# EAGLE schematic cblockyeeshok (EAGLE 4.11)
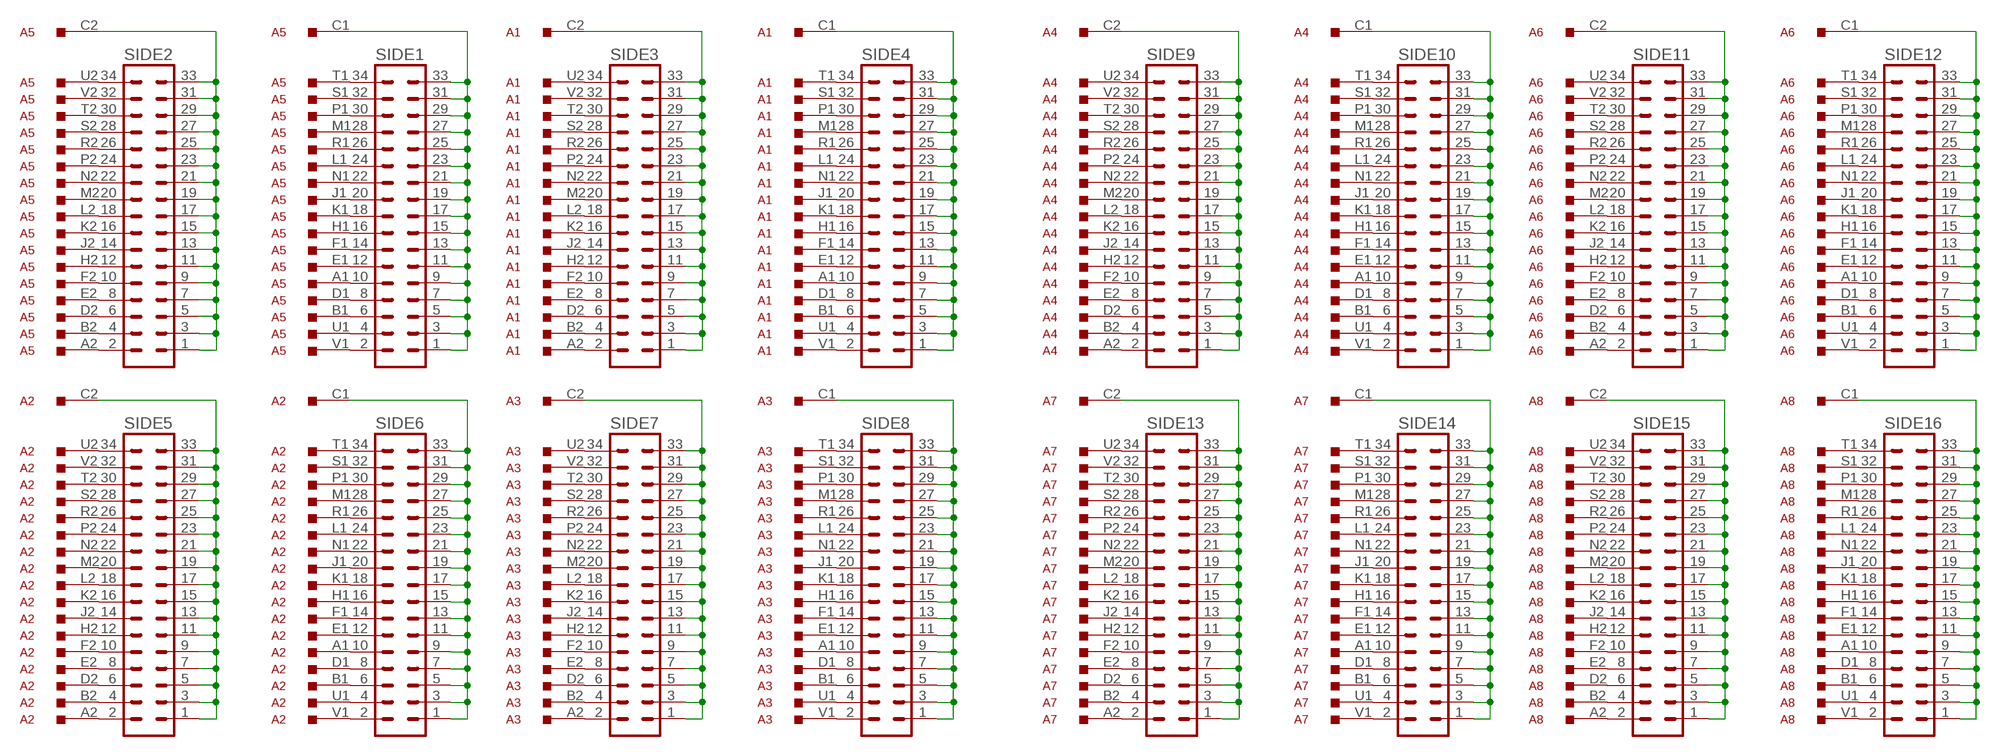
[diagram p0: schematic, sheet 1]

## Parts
A1  M916  [H807]
A2  M916  [H807]
A3  M916  [H807]
A4  M916  [H807]
A5  M916  [H807]
A6  M916  [H807]
A7  M916  [H807]
A8  M916  [H807]
SIDE1  MA17-2  [MA17-2]
SIDE2  MA17-2  [MA17-2]
SIDE3  MA17-2  [MA17-2]
SIDE4  MA17-2  [MA17-2]
SIDE5  MA17-2  [MA17-2]
SIDE6  MA17-2  [MA17-2]
SIDE7  MA17-2  [MA17-2]
SIDE8  MA17-2  [MA17-2]
SIDE9  MA17-2  [MA17-2]
SIDE10  MA17-2  [MA17-2]
SIDE11  MA17-2  [MA17-2]
SIDE12  MA17-2  [MA17-2]
SIDE13  MA17-2  [MA17-2]
SIDE14  MA17-2  [MA17-2]
SIDE15  MA17-2  [MA17-2]
SIDE16  MA17-2  [MA17-2]

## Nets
N$1: A5.C2 SIDE2.1 SIDE2.3 SIDE2.5 SIDE2.7 SIDE2.9 SIDE2.11 SIDE2.13 SIDE2.15 SIDE2.17 SIDE2.19 SIDE2.21 SIDE2.23 SIDE2.25 SIDE2.27 SIDE2.29 SIDE2.31 SIDE2.33
N$2: A5.A2 SIDE2.2
N$3: A5.B2 SIDE2.4
N$4: A5.D2 SIDE2.6
N$5: A5.E2 SIDE2.8
N$6: A5.F2 SIDE2.10
N$7: A5.H2 SIDE2.12
N$8: A5.J2 SIDE2.14
N$9: A5.K2 SIDE2.16
N$10: A5.L2 SIDE2.18
N$11: A5.M2 SIDE2.20
N$12: A5.N2 SIDE2.22
N$13: A5.P2 SIDE2.24
N$14: A5.R2 SIDE2.26
N$15: A5.S2 SIDE2.28
N$16: A5.T2 SIDE2.30
N$17: A5.U2 SIDE2.34
N$18: A5.V2 SIDE2.32
N$19: A5.A1 SIDE1.10
N$20: A5.B1 SIDE1.6
N$21: A5.D1 SIDE1.8
N$22: A5.E1 SIDE1.12
N$23: A5.F1 SIDE1.14
N$24: A5.H1 SIDE1.16
N$25: A5.J1 SIDE1.20
N$26: A5.K1 SIDE1.18
N$27: A5.L1 SIDE1.24
N$28: A5.M1 SIDE1.28
N$29: A5.N1 SIDE1.22
N$30: A5.P1 SIDE1.30
N$31: A5.R1 SIDE1.26
N$32: A5.S1 SIDE1.32
N$33: A5.T1 SIDE1.34
N$34: A5.U1 SIDE1.4
N$35: A5.V1 SIDE1.2
N$36: A5.C1 SIDE1.1 SIDE1.3 SIDE1.5 SIDE1.7 SIDE1.9 SIDE1.11 SIDE1.13 SIDE1.15 SIDE1.17 SIDE1.19 SIDE1.21 SIDE1.23 SIDE1.25 SIDE1.27 SIDE1.29 SIDE1.31 SIDE1.33
N$37: A1.C2 SIDE3.1 SIDE3.3 SIDE3.5 SIDE3.7 SIDE3.9 SIDE3.11 SIDE3.13 SIDE3.15 SIDE3.17 SIDE3.19 SIDE3.21 SIDE3.23 SIDE3.25 SIDE3.27 SIDE3.29 SIDE3.31 SIDE3.33
N$38: A1.A2 SIDE3.2
N$39: A1.B2 SIDE3.4
N$40: A1.D2 SIDE3.6
N$41: A1.E2 SIDE3.8
N$42: A1.F2 SIDE3.10
N$43: A1.H2 SIDE3.12
N$44: A1.J2 SIDE3.14
N$45: A1.K2 SIDE3.16
N$46: A1.L2 SIDE3.18
N$47: A1.M2 SIDE3.20
N$48: A1.N2 SIDE3.22
N$49: A1.P2 SIDE3.24
N$50: A1.R2 SIDE3.26
N$51: A1.S2 SIDE3.28
N$52: A1.T2 SIDE3.30
N$53: A1.U2 SIDE3.34
N$54: A1.V2 SIDE3.32
N$55: A1.A1 SIDE4.10
N$56: A1.B1 SIDE4.6
N$57: A1.D1 SIDE4.8
N$58: A1.E1 SIDE4.12
N$59: A1.F1 SIDE4.14
N$60: A1.H1 SIDE4.16
N$61: A1.J1 SIDE4.20
N$62: A1.K1 SIDE4.18
N$63: A1.L1 SIDE4.24
N$64: A1.M1 SIDE4.28
N$65: A1.N1 SIDE4.22
N$66: A1.P1 SIDE4.30
N$67: A1.R1 SIDE4.26
N$68: A1.S1 SIDE4.32
N$69: A1.T1 SIDE4.34
N$70: A1.U1 SIDE4.4
N$71: A1.V1 SIDE4.2
N$72: A1.C1 SIDE4.1 SIDE4.3 SIDE4.5 SIDE4.7 SIDE4.9 SIDE4.11 SIDE4.13 SIDE4.15 SIDE4.17 SIDE4.19 SIDE4.21 SIDE4.23 SIDE4.25 SIDE4.27 SIDE4.29 SIDE4.31 SIDE4.33
N$73: A2.C2 SIDE5.1 SIDE5.3 SIDE5.5 SIDE5.7 SIDE5.9 SIDE5.11 SIDE5.13 SIDE5.15 SIDE5.17 SIDE5.19 SIDE5.21 SIDE5.23 SIDE5.25 SIDE5.27 SIDE5.29 SIDE5.31 SIDE5.33
N$74: A2.A2 SIDE5.2
N$75: A2.B2 SIDE5.4
N$76: A2.D2 SIDE5.6
N$77: A2.E2 SIDE5.8
N$78: A2.F2 SIDE5.10
N$79: A2.H2 SIDE5.12
N$80: A2.J2 SIDE5.14
N$81: A2.K2 SIDE5.16
N$82: A2.L2 SIDE5.18
N$83: A2.M2 SIDE5.20
N$84: A2.N2 SIDE5.22
N$85: A2.P2 SIDE5.24
N$86: A2.R2 SIDE5.26
N$87: A2.S2 SIDE5.28
N$88: A2.T2 SIDE5.30
N$89: A2.U2 SIDE5.34
N$90: A2.V2 SIDE5.32
N$91: A2.A1 SIDE6.10
N$92: A2.B1 SIDE6.6
N$93: A2.D1 SIDE6.8
N$94: A2.E1 SIDE6.12
N$95: A2.F1 SIDE6.14
N$96: A2.H1 SIDE6.16
N$97: A2.J1 SIDE6.20
N$98: A2.K1 SIDE6.18
N$99: A2.L1 SIDE6.24
N$100: A2.M1 SIDE6.28
N$101: A2.N1 SIDE6.22
N$102: A2.P1 SIDE6.30
N$103: A2.R1 SIDE6.26
N$104: A2.S1 SIDE6.32
N$105: A2.T1 SIDE6.34
N$106: A2.U1 SIDE6.4
N$107: A2.V1 SIDE6.2
N$108: A2.C1 SIDE6.1 SIDE6.3 SIDE6.5 SIDE6.7 SIDE6.9 SIDE6.11 SIDE6.13 SIDE6.15 SIDE6.17 SIDE6.19 SIDE6.21 SIDE6.23 SIDE6.25 SIDE6.27 SIDE6.29 SIDE6.31 SIDE6.33
N$109: A3.C2 SIDE7.1 SIDE7.3 SIDE7.5 SIDE7.7 SIDE7.9 SIDE7.11 SIDE7.13 SIDE7.15 SIDE7.17 SIDE7.19 SIDE7.21 SIDE7.23 SIDE7.25 SIDE7.27 SIDE7.29 SIDE7.31 SIDE7.33
N$110: A3.A2 SIDE7.2
N$111: A3.B2 SIDE7.4
N$112: A3.D2 SIDE7.6
N$113: A3.E2 SIDE7.8
N$114: A3.F2 SIDE7.10
N$115: A3.H2 SIDE7.12
N$116: A3.J2 SIDE7.14
N$117: A3.K2 SIDE7.16
N$118: A3.L2 SIDE7.18
N$119: A3.M2 SIDE7.20
N$120: A3.N2 SIDE7.22
N$121: A3.P2 SIDE7.24
N$122: A3.R2 SIDE7.26
N$123: A3.S2 SIDE7.28
N$124: A3.T2 SIDE7.30
N$125: A3.U2 SIDE7.34
N$126: A3.V2 SIDE7.32
N$127: A3.A1 SIDE8.10
N$128: A3.B1 SIDE8.6
N$129: A3.D1 SIDE8.8
N$130: A3.E1 SIDE8.12
N$131: A3.F1 SIDE8.14
N$132: A3.H1 SIDE8.16
N$133: A3.J1 SIDE8.20
N$134: A3.K1 SIDE8.18
N$135: A3.L1 SIDE8.24
N$136: A3.M1 SIDE8.28
N$137: A3.N1 SIDE8.22
N$138: A3.P1 SIDE8.30
N$139: A3.R1 SIDE8.26
N$140: A3.S1 SIDE8.32
N$141: A3.T1 SIDE8.34
N$142: A3.U1 SIDE8.4
N$143: A3.V1 SIDE8.2
N$144: A3.C1 SIDE8.1 SIDE8.3 SIDE8.5 SIDE8.7 SIDE8.9 SIDE8.11 SIDE8.13 SIDE8.15 SIDE8.17 SIDE8.19 SIDE8.21 SIDE8.23 SIDE8.25 SIDE8.27 SIDE8.29 SIDE8.31 SIDE8.33
N$145: A4.C2 SIDE9.1 SIDE9.3 SIDE9.5 SIDE9.7 SIDE9.9 SIDE9.11 SIDE9.13 SIDE9.15 SIDE9.17 SIDE9.19 SIDE9.21 SIDE9.23 SIDE9.25 SIDE9.27 SIDE9.29 SIDE9.31 SIDE9.33
N$146: A4.A2 SIDE9.2
N$147: A4.B2 SIDE9.4
N$148: A4.D2 SIDE9.6
N$149: A4.E2 SIDE9.8
N$150: A4.F2 SIDE9.10
N$151: A4.H2 SIDE9.12
N$152: A4.J2 SIDE9.14
N$153: A4.K2 SIDE9.16
N$154: A4.L2 SIDE9.18
N$155: A4.M2 SIDE9.20
N$156: A4.N2 SIDE9.22
N$157: A4.P2 SIDE9.24
N$158: A4.R2 SIDE9.26
N$159: A4.S2 SIDE9.28
N$160: A4.T2 SIDE9.30
N$161: A4.U2 SIDE9.34
N$162: A4.V2 SIDE9.32
N$163: A4.A1 SIDE10.10
N$164: A4.B1 SIDE10.6
N$165: A4.D1 SIDE10.8
N$166: A4.E1 SIDE10.12
N$167: A4.F1 SIDE10.14
N$168: A4.H1 SIDE10.16
N$169: A4.J1 SIDE10.20
N$170: A4.K1 SIDE10.18
N$171: A4.L1 SIDE10.24
N$172: A4.M1 SIDE10.28
N$173: A4.N1 SIDE10.22
N$174: A4.P1 SIDE10.30
N$175: A4.R1 SIDE10.26
N$176: A4.S1 SIDE10.32
N$177: A4.T1 SIDE10.34
N$178: A4.U1 SIDE10.4
N$179: A4.V1 SIDE10.2
N$180: A4.C1 SIDE10.1 SIDE10.3 SIDE10.5 SIDE10.7 SIDE10.9 SIDE10.11 SIDE10.13 SIDE10.15 SIDE10.17 SIDE10.19 SIDE10.21 SIDE10.23 SIDE10.25 SIDE10.27 SIDE10.29 SIDE10.31 SIDE10.33
N$181: A6.C2 SIDE11.1 SIDE11.3 SIDE11.5 SIDE11.7 SIDE11.9 SIDE11.11 SIDE11.13 SIDE11.15 SIDE11.17 SIDE11.19 SIDE11.21 SIDE11.23 SIDE11.25 SIDE11.27 SIDE11.29 SIDE11.31 SIDE11.33
N$182: A6.A2 SIDE11.2
N$183: A6.B2 SIDE11.4
N$184: A6.D2 SIDE11.6
N$185: A6.E2 SIDE11.8
N$186: A6.F2 SIDE11.10
N$187: A6.H2 SIDE11.12
N$188: A6.J2 SIDE11.14
N$189: A6.K2 SIDE11.16
N$190: A6.L2 SIDE11.18
N$191: A6.M2 SIDE11.20
N$192: A6.N2 SIDE11.22
N$193: A6.P2 SIDE11.24
N$194: A6.R2 SIDE11.26
N$195: A6.S2 SIDE11.28
N$196: A6.T2 SIDE11.30
N$197: A6.U2 SIDE11.34
N$198: A6.V2 SIDE11.32
N$199: A6.A1 SIDE12.10
N$200: A6.B1 SIDE12.6
N$201: A6.D1 SIDE12.8
N$202: A6.E1 SIDE12.12
N$203: A6.F1 SIDE12.14
N$204: A6.H1 SIDE12.16
N$205: A6.J1 SIDE12.20
N$206: A6.K1 SIDE12.18
N$207: A6.L1 SIDE12.24
N$208: A6.M1 SIDE12.28
N$209: A6.N1 SIDE12.22
N$210: A6.P1 SIDE12.30
N$211: A6.R1 SIDE12.26
N$212: A6.S1 SIDE12.32
N$213: A6.T1 SIDE12.34
N$214: A6.U1 SIDE12.4
N$215: A6.V1 SIDE12.2
N$216: A6.C1 SIDE12.1 SIDE12.3 SIDE12.5 SIDE12.7 SIDE12.9 SIDE12.11 SIDE12.13 SIDE12.15 SIDE12.17 SIDE12.19 SIDE12.21 SIDE12.23 SIDE12.25 SIDE12.27 SIDE12.29 SIDE12.31 SIDE12.33
N$217: A7.C2 SIDE13.1 SIDE13.3 SIDE13.5 SIDE13.7 SIDE13.9 SIDE13.11 SIDE13.13 SIDE13.15 SIDE13.17 SIDE13.19 SIDE13.21 SIDE13.23 SIDE13.25 SIDE13.27 SIDE13.29 SIDE13.31 SIDE13.33
N$218: A7.A2 SIDE13.2
N$219: A7.B2 SIDE13.4
N$220: A7.D2 SIDE13.6
N$221: A7.E2 SIDE13.8
N$222: A7.F2 SIDE13.10
N$223: A7.H2 SIDE13.12
N$224: A7.J2 SIDE13.14
N$225: A7.K2 SIDE13.16
N$226: A7.L2 SIDE13.18
N$227: A7.M2 SIDE13.20
N$228: A7.N2 SIDE13.22
N$229: A7.P2 SIDE13.24
N$230: A7.R2 SIDE13.26
N$231: A7.S2 SIDE13.28
N$232: A7.T2 SIDE13.30
N$233: A7.U2 SIDE13.34
N$234: A7.V2 SIDE13.32
N$235: A7.A1 SIDE14.10
N$236: A7.B1 SIDE14.6
N$237: A7.D1 SIDE14.8
N$238: A7.E1 SIDE14.12
N$239: A7.F1 SIDE14.14
N$240: A7.H1 SIDE14.16
N$241: A7.J1 SIDE14.20
N$242: A7.K1 SIDE14.18
N$243: A7.L1 SIDE14.24
N$244: A7.M1 SIDE14.28
N$245: A7.N1 SIDE14.22
N$246: A7.P1 SIDE14.30
N$247: A7.R1 SIDE14.26
N$248: A7.S1 SIDE14.32
N$249: A7.T1 SIDE14.34
N$250: A7.U1 SIDE14.4
N$251: A7.V1 SIDE14.2
N$252: A7.C1 SIDE14.1 SIDE14.3 SIDE14.5 SIDE14.7 SIDE14.9 SIDE14.11 SIDE14.13 SIDE14.15 SIDE14.17 SIDE14.19 SIDE14.21 SIDE14.23 SIDE14.25 SIDE14.27 SIDE14.29 SIDE14.31 SIDE14.33
N$253: A8.C2 SIDE15.1 SIDE15.3 SIDE15.5 SIDE15.7 SIDE15.9 SIDE15.11 SIDE15.13 SIDE15.15 SIDE15.17 SIDE15.19 SIDE15.21 SIDE15.23 SIDE15.25 SIDE15.27 SIDE15.29 SIDE15.31 SIDE15.33
N$254: A8.A2 SIDE15.2
N$255: A8.B2 SIDE15.4
N$256: A8.D2 SIDE15.6
N$257: A8.E2 SIDE15.8
N$258: A8.F2 SIDE15.10
N$259: A8.H2 SIDE15.12
N$260: A8.J2 SIDE15.14
N$261: A8.K2 SIDE15.16
N$262: A8.L2 SIDE15.18
N$263: A8.M2 SIDE15.20
N$264: A8.N2 SIDE15.22
N$265: A8.P2 SIDE15.24
N$266: A8.R2 SIDE15.26
N$267: A8.S2 SIDE15.28
N$268: A8.T2 SIDE15.30
N$269: A8.U2 SIDE15.34
N$270: A8.V2 SIDE15.32
N$271: A8.A1 SIDE16.10
N$272: A8.B1 SIDE16.6
N$273: A8.D1 SIDE16.8
N$274: A8.E1 SIDE16.12
N$275: A8.F1 SIDE16.14
N$276: A8.H1 SIDE16.16
N$277: A8.J1 SIDE16.20
N$278: A8.K1 SIDE16.18
N$279: A8.L1 SIDE16.24
N$280: A8.M1 SIDE16.28
N$281: A8.N1 SIDE16.22
N$282: A8.P1 SIDE16.30
N$283: A8.R1 SIDE16.26
N$284: A8.S1 SIDE16.32
N$285: A8.T1 SIDE16.34
N$286: A8.U1 SIDE16.4
N$287: A8.V1 SIDE16.2
N$288: A8.C1 SIDE16.1 SIDE16.3 SIDE16.5 SIDE16.7 SIDE16.9 SIDE16.11 SIDE16.13 SIDE16.15 SIDE16.17 SIDE16.19 SIDE16.21 SIDE16.23 SIDE16.25 SIDE16.27 SIDE16.29 SIDE16.31 SIDE16.33

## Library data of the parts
A1-A8 = dec-m:M916: Simple 36 pin connector/wire cable
SIDE1-SIDE16 = con-lstb:MA17-2: PIN HEADER

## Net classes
1 Power: width 0.305 mm, drill 0.305 mm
